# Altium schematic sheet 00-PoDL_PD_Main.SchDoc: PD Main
size A2; Date: Mon 1st Aug, 2020; CompanyName: RGT Supply and Service Ltd.; Engineer: Nattawut; Address1: 285/95 M.3 T.Tonpao Sankampaeng; Address2: Chiangmai 50130 Thailand Tel.+66 89 1645339; Revision: 1.5; SheetNumber: 0; SheetTotal: 4; ContentRev1: Original Document; dateREV1: 01-01-2023; NameRev1: Nattawut; NameRev3: Nattawut; NameRev2: Nattawut; NameRev4: Nattawut; NameRev5: Nattawut; NameRev6: Nattawut; dateREV2: 20-04-2023; dateREV3: 04-11-2023; dateREV4: 14-05-2024; dateREV5: 05-07-2024; dateREV6: 16-09-2024; ContentRev2: Change to AD controller; ContentRev3: Update Power Coupling; ContentRev4: Improve for EMC ability; ContentRev5: Add D31, Replace FB7 to R164; ContentRev6: Improve for EMC ability; Rev1: 1.0; Rev2: 1.1; Rev3: 1.2; Rev4: 1.3; Rev5: 1.4; Rev6: 1.5; Project: PoDL; PageSetup: Record=PageOptions¦CenterHorizontal=True¦CenterVertical=True¦PrintScale=0.73¦XCorrection=1.00¦YCorrection=1.00¦PrintKind=0¦BorderSize=5000000¦LeftOffset=0¦BottomOffset=0¦Orientation=2¦PaperLength=1000¦PaperWidth=1000¦Scale=100¦PaperSource=7¦PrintQuality=-3¦MediaType=1¦DitherType=10¦PrintScaleMode=1¦PaperKind=A3¦PaperIndex=8
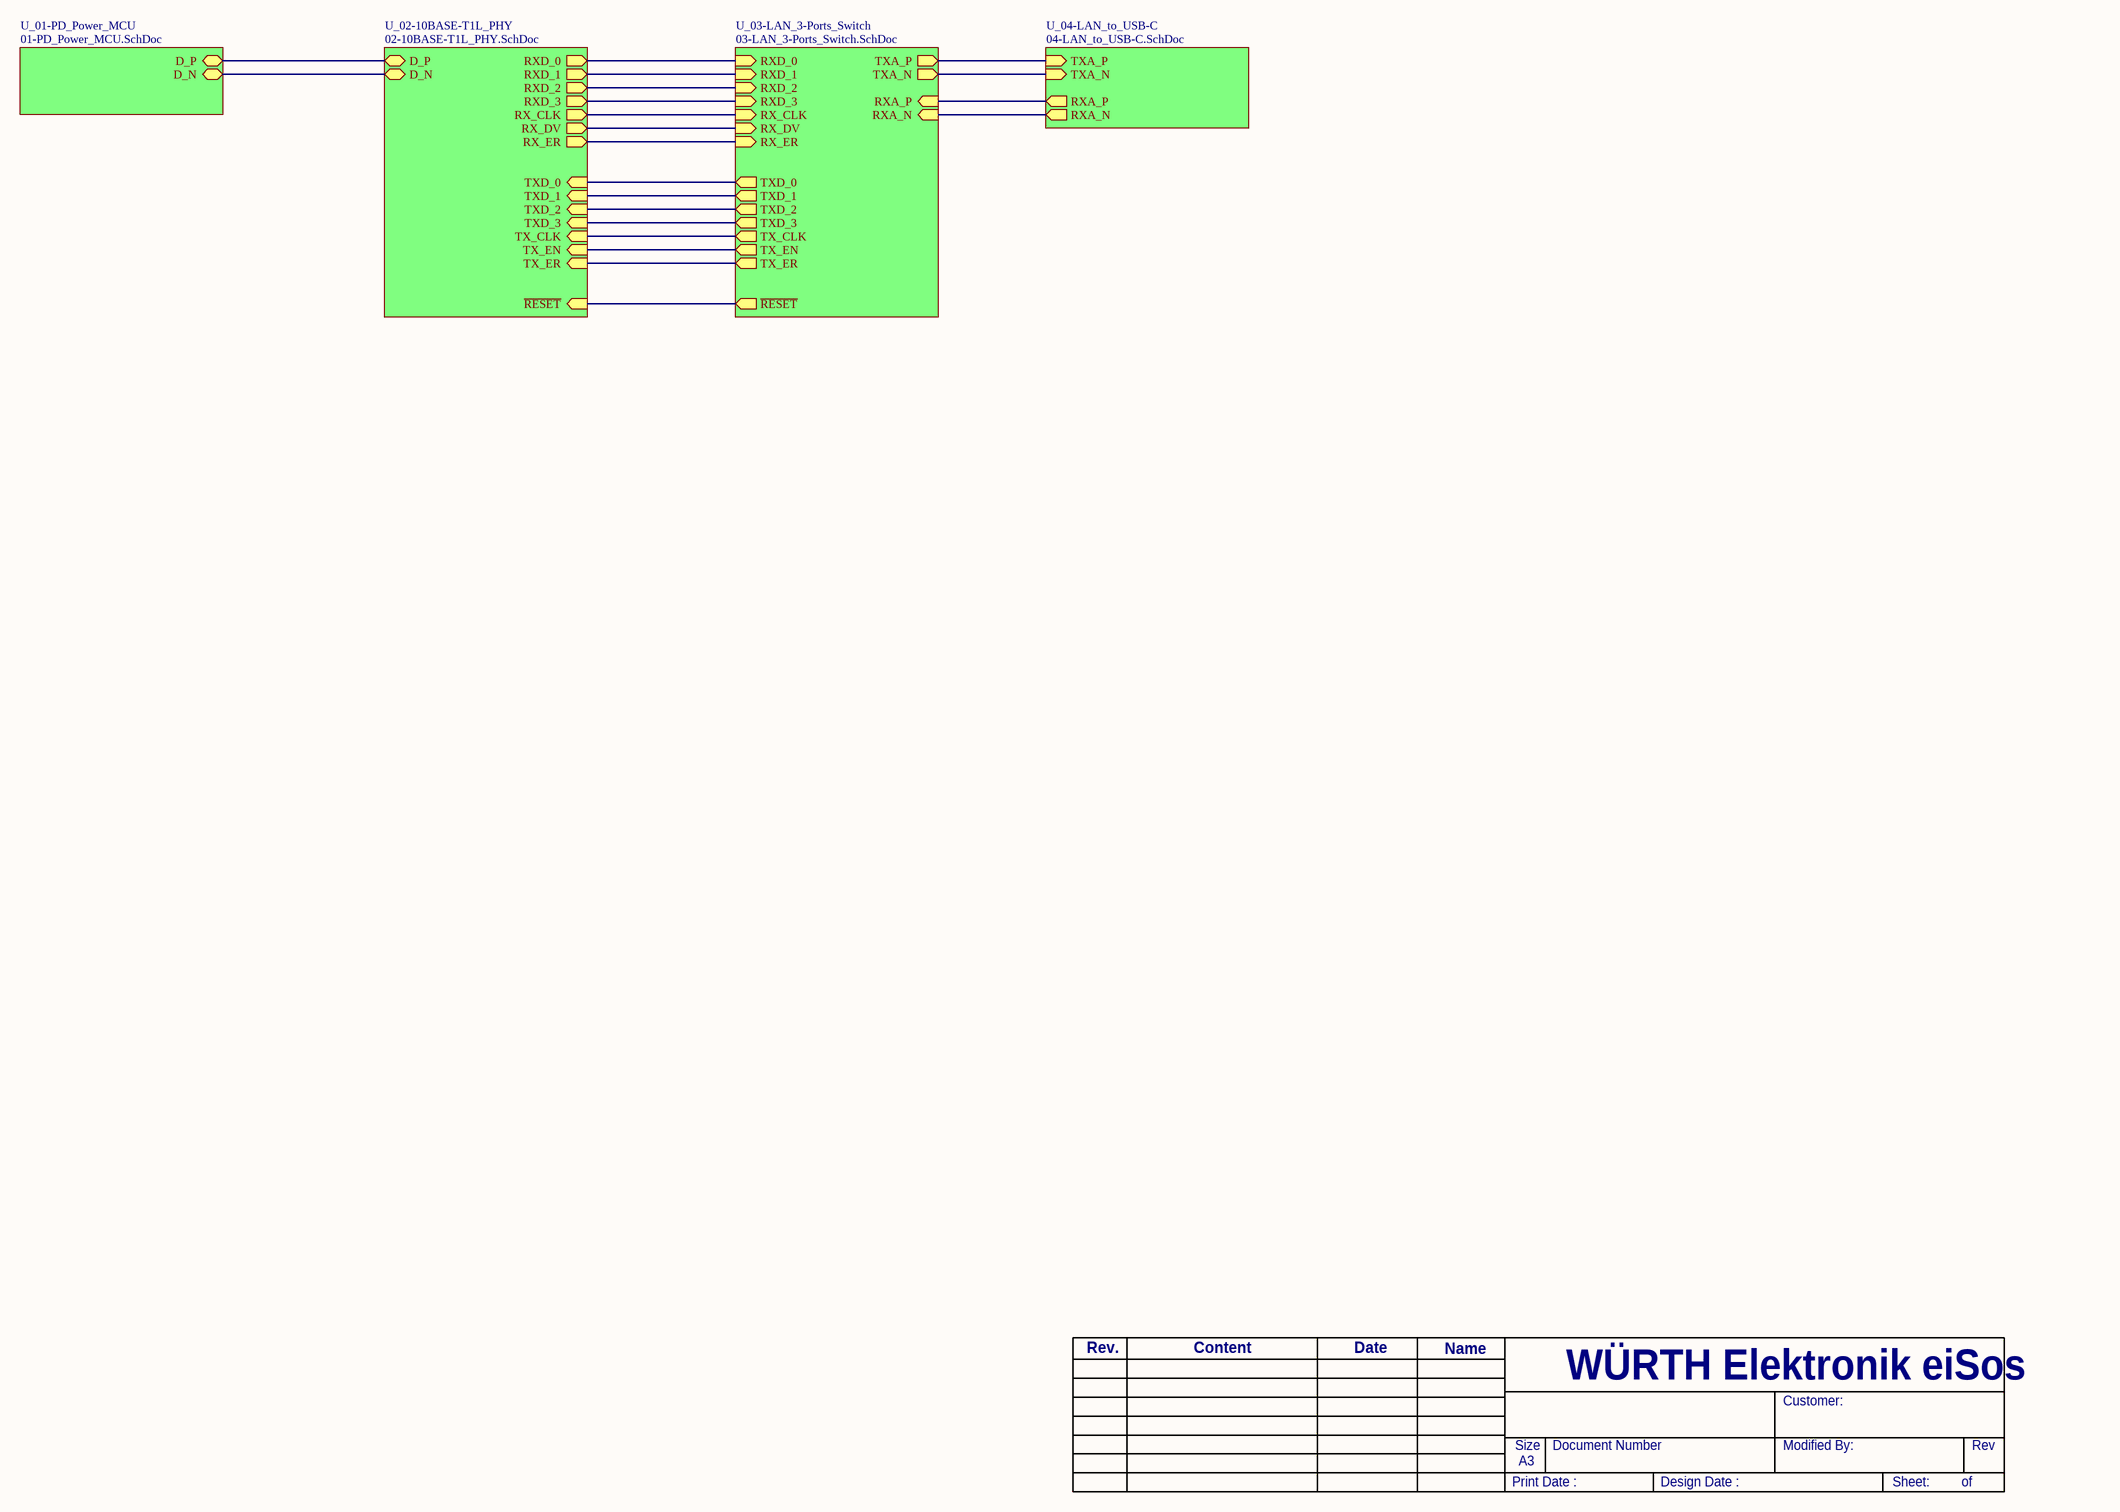
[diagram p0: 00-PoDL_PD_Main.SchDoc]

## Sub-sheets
U_01-PD_Power_MCU = 01-PD_Power_MCU.SchDoc: D_P (bidir), D_N (bidir)
U_02-10BASE-T1L_PHY = 02-10BASE-T1L_PHY.SchDoc: RXD_0 (out), RXD_1 (out), RXD_2 (out), RXD_3 (out), RX_CLK (out), RX_DV (out), RX_ER (out), TX_ER (in), TX_EN (in), TX_CLK (in), TXD_0 (in), TXD_1 (in), TXD_3 (in), TXD_2 (in), ~{RESET} (in), D_P (bidir), D_N (bidir)
U_03-LAN_3-Ports_Switch = 03-LAN_3-Ports_Switch.SchDoc: TXA_N (out), TXA_P (out), RXA_N (in), RXA_P (in), ~{RESET} (out), RXD_1 (in), TXD_2 (out), TXD_3 (out), RX_ER (in), RX_DV (in), RX_CLK (in), RXD_0 (in), RXD_3 (in), TXD_0 (out), TX_EN (out), TX_ER (out), RXD_2 (in), TXD_1 (out), TX_CLK (out)
U_04-LAN_to_USB-C = 04-LAN_to_USB-C.SchDoc: TXA_N (in), TXA_P (in), RXA_N (out), RXA_P (out)

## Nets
(unnamed): sheet U_01-PD_Power_MCU/D_P, sheet U_02-10BASE-T1L_PHY/D_P
(unnamed): sheet U_01-PD_Power_MCU/D_N, sheet U_02-10BASE-T1L_PHY/D_N  [a separate net that carries the same name]
(unnamed): sheet U_02-10BASE-T1L_PHY/RXD_0, sheet U_03-LAN_3-Ports_Switch/RXD_0  [a separate net that carries the same name]
(unnamed): sheet U_02-10BASE-T1L_PHY/RXD_1, sheet U_03-LAN_3-Ports_Switch/RXD_1  [a separate net that carries the same name]
(unnamed): sheet U_02-10BASE-T1L_PHY/RXD_2, sheet U_03-LAN_3-Ports_Switch/RXD_2  [a separate net that carries the same name]
(unnamed): sheet U_02-10BASE-T1L_PHY/RXD_3, sheet U_03-LAN_3-Ports_Switch/RXD_3  [a separate net that carries the same name]
(unnamed): sheet U_02-10BASE-T1L_PHY/RX_CLK, sheet U_03-LAN_3-Ports_Switch/RX_CLK  [a separate net that carries the same name]
(unnamed): sheet U_02-10BASE-T1L_PHY/RX_DV, sheet U_03-LAN_3-Ports_Switch/RX_DV  [a separate net that carries the same name]
(unnamed): sheet U_02-10BASE-T1L_PHY/RX_ER, sheet U_03-LAN_3-Ports_Switch/RX_ER  [a separate net that carries the same name]
(unnamed): sheet U_02-10BASE-T1L_PHY/TX_ER, sheet U_03-LAN_3-Ports_Switch/TX_ER  [a separate net that carries the same name]
(unnamed): sheet U_02-10BASE-T1L_PHY/TX_EN, sheet U_03-LAN_3-Ports_Switch/TX_EN  [a separate net that carries the same name]
(unnamed): sheet U_02-10BASE-T1L_PHY/TX_CLK, sheet U_03-LAN_3-Ports_Switch/TX_CLK  [a separate net that carries the same name]
(unnamed): sheet U_02-10BASE-T1L_PHY/TXD_0, sheet U_03-LAN_3-Ports_Switch/TXD_0  [a separate net that carries the same name]
(unnamed): sheet U_02-10BASE-T1L_PHY/TXD_1, sheet U_03-LAN_3-Ports_Switch/TXD_1  [a separate net that carries the same name]
(unnamed): sheet U_02-10BASE-T1L_PHY/TXD_3, sheet U_03-LAN_3-Ports_Switch/TXD_3  [a separate net that carries the same name]
(unnamed): sheet U_02-10BASE-T1L_PHY/TXD_2, sheet U_03-LAN_3-Ports_Switch/TXD_2  [a separate net that carries the same name]
(unnamed): sheet U_02-10BASE-T1L_PHY/~{RESET}, sheet U_03-LAN_3-Ports_Switch/~{RESET}  [a separate net that carries the same name]
(unnamed): sheet U_03-LAN_3-Ports_Switch/TXA_N, sheet U_04-LAN_to_USB-C/TXA_N  [a separate net that carries the same name]
(unnamed): sheet U_03-LAN_3-Ports_Switch/TXA_P, sheet U_04-LAN_to_USB-C/TXA_P  [a separate net that carries the same name]
(unnamed): sheet U_03-LAN_3-Ports_Switch/RXA_N, sheet U_04-LAN_to_USB-C/RXA_N  [a separate net that carries the same name]
(unnamed): sheet U_03-LAN_3-Ports_Switch/RXA_P, sheet U_04-LAN_to_USB-C/RXA_P  [a separate net that carries the same name]

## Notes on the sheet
- Rev.
- Content
- Date
- Name
- WÜRTH Elektronik eiSos
- Customer:
- Print Date :
- Size
- A3
- Document Number
- Design Date :
- Modified By:
- Sheet:
- of
- Rev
